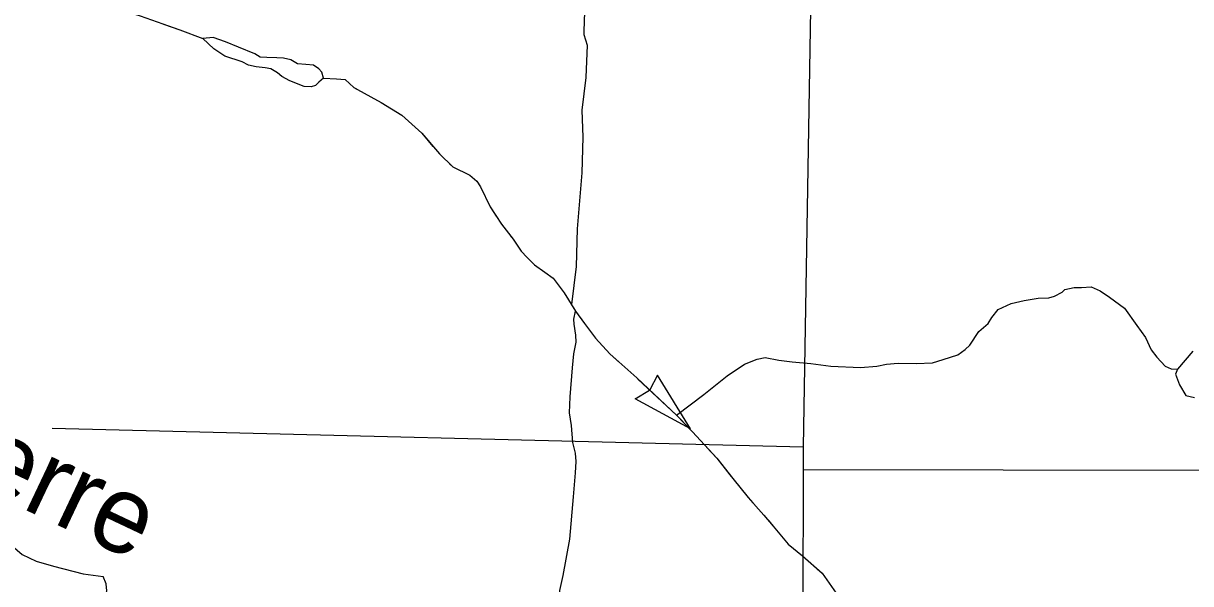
# Model space of a CAD drawing. Extents: x 1369979 to 1371646, y 379997 to 381064.
# Drawn here: x 1370868.8 to 1370943.5, y 380472 to 380507.9 of the extents above; entities that cross this region are included whole.
import ezdxf

# ---------------------------------------------------------------- set-up
doc = ezdxf.new("R2010")
doc.units = 0
doc.layers.add('R_Border Notes', color=7, linetype='Continuous')

msp = doc.modelspace()

# ---------------------------------------------------------------- linework, layer by layer
at = {"layer": 'R_Border Notes'}
for p, q in [((1370909.433, 380485.355), (1370908.926, 380484.413)), ((1370911.546, 380481.933), (1370909.433, 380485.355)), ((1370908.005, 380483.84), (1370908.916, 380484.403)), ((1370911.546, 380481.933), (1370908.005, 380483.84))]:
    msp.add_line(p, q, dxfattribs=at)
for points in [[(1370920.37, 380581.601), (1370919.796, 380543.55), (1370919.771, 380541.901), (1370918.746, 380480.774), (1370918.743, 380479.316), (1370918.699, 380461.915)], [(1370906.71, 380521.204), (1370907.559, 380519.656), (1370907.771, 380518.534), (1370907.589, 380517.169), (1370906.74, 380514.923), (1370906.013, 380512.86), (1370905.134, 380510.16), (1370904.831, 380509.128), (1370904.74, 380508.218), (1370904.71, 380507.156)], [(1370865.68, 380511.977), (1370868.399, 380510.956), (1370870.188, 380510.335), (1370871.533, 380509.891), (1370872.586, 380509.561), (1370876.322, 380508.367), (1370878.85, 380507.464), (1370880.328, 380506.917)], [(1370877.817, 380507.833), (1370878.85, 380507.464), (1370880.328, 380506.917)], [(1370904.71, 380507.156), (1370904.922, 380506.476), (1370904.831, 380504.413), (1370904.588, 380502.32), (1370904.649, 380500.59), (1370904.588, 380498.315), (1370904.285, 380494.735), (1370904.225, 380492.307), (1370903.921, 380489.884)], [(1370880.987, 380506.967), (1370880.328, 380506.917)], [(1370881.032, 380506.257), (1370880.328, 380506.917)], [(1370888.053, 380504.379), (1370887.949, 380504.748), (1370887.742, 380504.97), (1370887.403, 380505.192), (1370886.915, 380505.251), (1370886.397, 380505.281), (1370885.969, 380505.547), (1370885.496, 380505.65), (1370885.067, 380505.68), (1370884.417, 380505.695), (1370883.988, 380505.724), (1370883.648, 380505.917), (1370882.613, 380506.346), (1370881.786, 380506.686), (1370880.987, 380506.967)], [(1370888.053, 380504.379), (1370887.742, 380504.112), (1370887.536, 380503.89), (1370887.269, 380503.816), (1370886.811, 380503.845), (1370885.895, 380504.201), (1370885.392, 380504.482), (1370885.111, 380504.718), (1370884.683, 380504.97), (1370884.313, 380505.029), (1370883.751, 380505.088), (1370883.249, 380505.192), (1370882.85, 380505.414), (1370881.741, 380505.784), (1370881.032, 380506.257)], [(1370888.053, 380504.379), (1370888.873, 380504.334), (1370889.435, 380504.275), (1370889.997, 380503.78)], [(1370888.053, 380504.379), (1370888.873, 380504.334), (1370889.435, 380504.275), (1370889.997, 380503.78), (1370890.159, 380503.69)], [(1370889.997, 380503.78), (1370891.741, 380502.804), (1370893.071, 380502.005), (1370894.342, 380500.851), (1370895.466, 380499.519), (1370896.323, 380498.691), (1370897.41, 380498.158)], [(1370891.509, 380502.934), (1370891.741, 380502.804), (1370893.071, 380502.005), (1370894.342, 380500.851), (1370895.055, 380500.006)], [(1370896.12, 380498.887), (1370896.323, 380498.691), (1370897.41, 380498.158), (1370897.868, 380497.774), (1370898.104, 380497.419), (1370898.725, 380496.131), (1370899.099, 380495.546)], [(1370897.41, 380498.158), (1370897.868, 380497.774), (1370898.104, 380497.419), (1370898.725, 380496.131), (1370899.435, 380495.022), (1370900.189, 380494.06), (1370900.691, 380493.305), (1370901.075, 380492.891), (1370901.548, 380492.433), (1370902.214, 380491.944), (1370902.746, 380491.56), (1370903.444, 380490.635)], [(1370900.005, 380494.294), (1370900.189, 380494.06), (1370900.691, 380493.305), (1370901.075, 380492.891), (1370901.548, 380492.433), (1370902.214, 380491.944), (1370902.746, 380491.56), (1370903.186, 380490.976)], [(1370910.635, 380482.792), (1370912.393, 380484.127), (1370913.893, 380485.31), (1370915, 380486.069), (1370915.803, 380486.388), (1370916.318, 380486.494), (1370917.182, 380486.327), (1370918.046, 380486.221), (1370919.228, 380486.099), (1370920.516, 380485.948), (1370922.426, 380485.857), (1370923.456, 380485.932), (1370924.078, 380486.069), (1370924.835, 380486.13), (1370925.987, 380486.115), (1370927.018, 380486.145), (1370927.715, 380486.357), (1370928.654, 380486.661), (1370929.109, 380486.994), (1370929.412, 380487.283), (1370929.988, 380488.162), (1370930.579, 380488.663), (1370930.822, 380489.058), (1370931.231, 380489.573), (1370932.064, 380489.953), (1370932.898, 380490.135), (1370933.777, 380490.286), (1370934.459, 380490.301), (1370934.838, 380490.423), (1370935.323, 380490.681), (1370935.49, 380490.848), (1370936.096, 380490.969), (1370936.566, 380490.969), (1370937.172, 380491.014), (1370937.748, 380490.757), (1370938.354, 380490.362), (1370939.309, 380489.649)], [(1370903.444, 380490.635), (1370904.186, 380489.467), (1370904.747, 380488.663), (1370905.467, 380487.728), (1370906.383, 380486.722), (1370908.098, 380485.183), (1370910.635, 380482.792), (1370911.675, 380481.736)], [(1370903.838, 380483.971), (1370903.989, 380485.841), (1370904.08, 380486.721), (1370904.217, 380487.465), (1370904.201, 380487.92), (1370904.095, 380488.633), (1370904.08, 380488.951), (1370904.186, 380489.467)], [(1370904.044, 380489.69), (1370904.186, 380489.467), (1370904.747, 380488.663), (1370905.467, 380487.728), (1370906.383, 380486.722), (1370907.019, 380486.151)], [(1370939.309, 380489.649), (1370940.101, 380488.542), (1370940.662, 380487.768), (1370941.026, 380486.979), (1370941.374, 380486.524), (1370941.92, 380485.948), (1370942.299, 380485.766), (1370942.693, 380485.75)], [(1370943.678, 380486.888), (1370942.708, 380485.75)], [(1370942.693, 380485.75), (1370942.572, 380485.417), (1370942.829, 380484.734), (1370943.238, 380484.067), (1370943.784, 380483.93)], [(1370908.169, 380485.116), (1370910.635, 380482.792), (1370911.514, 380481.9)], [(1370903.807, 380474.866), (1370904.05, 380477.584), (1370904.186, 380479.101), (1370904.217, 380479.829), (1370904.171, 380480.36), (1370904.004, 380481.058), (1370903.913, 380482.151), (1370903.792, 380482.955), (1370903.838, 380483.971)], [(1370870.679, 380481.975), (1370918.746, 380480.774)], [(1370911.675, 380481.736), (1370913.213, 380480.049), (1370914.247, 380478.747), (1370915.223, 380477.534), (1370916.228, 380476.41), (1370916.819, 380475.699), (1370917.795, 380474.545), (1370918.711, 380473.806), (1370919.953, 380472.681), (1370921.017, 380471.202), (1370922.141, 380469.9), (1370922.968, 380469.13), (1370924.003, 380468.036), (1370924.535, 380467), (1370925.215, 380465.964), (1370926.072, 380465.047), (1370926.576, 380464.018)], [(1370912.562, 380480.763), (1370913.213, 380480.049), (1370914.055, 380478.989)], [(1370914.055, 380478.989), (1370914.247, 380478.747), (1370915.223, 380477.534), (1370915.526, 380477.195)], [(1370918.743, 380479.316), (1370957.173, 380479.251)], [(1370861.644, 380478.069), (1370862.662, 380478.131), (1370863.166, 380478.045), (1370864.001, 380477.598), (1370864.922, 380476.661), (1370865.872, 380476.027), (1370868.133, 380474.442), (1370868.766, 380473.88), (1370869.673, 380473.448), (1370870.781, 380473.131), (1370872.679, 380472.646)], [(1370916.544, 380476.03), (1370916.819, 380475.699), (1370917.795, 380474.545), (1370918.711, 380473.806), (1370919.839, 380472.784)], [(1370903.019, 380466.604), (1370903.14, 380467.175), (1370903.034, 380468.965), (1370903.065, 380470.224), (1370903.171, 380471.589), (1370903.398, 380472.545), (1370903.807, 380474.866)], [(1370872.679, 380472.646), (1370873.96, 380472.487)], [(1370874.881, 380466.924), (1370874.968, 380468.095), (1370874.752, 380468.787), (1370874.593, 380469.421), (1370874.392, 380469.825), (1370874.061, 380470.487), (1370874.061, 380470.804), (1370874.176, 380471.554), (1370874.147, 380472.015), (1370873.96, 380472.487)]]:
    msp.add_lwpolyline(points, dxfattribs=at)

# ---------------------------------------------------------------- texts
msp.add_text('Terre', height=4.95, rotation=334.66651, dxfattribs=at).set_placement((1370861.655, 380480.202))

doc.saveas('drawing.dxf')
